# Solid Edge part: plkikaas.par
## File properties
Author: KULL
Template: Iso Metric Part.par
Last saved by: KULL
Revision: 7
Application: Solid Edge
Accuracy: 0,990
Face Style: Model Default
Fill Style: Normal
Coef. of Thermal Exp: 0.0
Thermal Conductivity: 0.0
Specific Heat: 0.0
Modulus of Elasticity: 0.0
Poisson's Ratio: 0.0
Yield Stress: 0.0
Ultimate Stress: 0.0
Elongation: 0.0
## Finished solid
Body 1: solid body, 32 faces, 44 edges, 16 vertices, 2 separate solids.
  Faces by surface: plane 22, cylinder 10
  Edges by curve: line 24, circle 20
Bounding box of the edges (mm): 96.000 x 84.087 x 24.824, from (-48, -42.0434, 60.5862) to (48, 42.0434, 85.41).
Cylindrical faces by radius (mm): R6 x10
Planar faces by outward normal: +x 2, -x 2, oblique 18
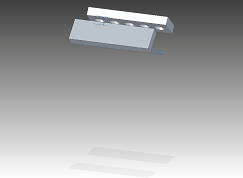
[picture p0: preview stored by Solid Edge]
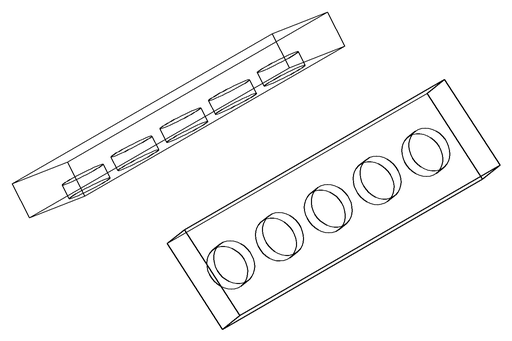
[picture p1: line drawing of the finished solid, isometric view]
